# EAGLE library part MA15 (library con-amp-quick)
AMP QUICK CONNECTOR
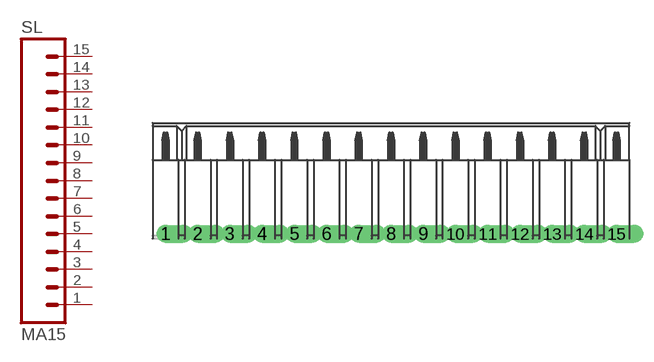
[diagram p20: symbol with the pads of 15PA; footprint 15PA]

Designator prefix SL

## MA15  [15PA]
1  1  pas
2  2  pas
3  3  pas
4  4  pas
5  5  pas
6  6  pas
7  7  pas
8  8  pas
9  9  pas
10  10  pas
11  11  pas
12  12  pas
13  13  pas
14  14  pas
15  15  pas

## Footprint 15PA (pad centres in mm)
AMP QUICK CONNECTOR
drill 0.914 offset: 1 -17.78,0; 2 -15.24,0; 3 -12.7,0; 4 -10.16,0; 5 -7.62,0; 6 -5.08,0; 7 -2.54,0; 8 0,0; 9 2.54,0; 10 5.08,0; 11 7.62,0; 12 10.16,0; 13 12.7,0; 14 15.24,0; 15 17.78,0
